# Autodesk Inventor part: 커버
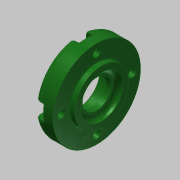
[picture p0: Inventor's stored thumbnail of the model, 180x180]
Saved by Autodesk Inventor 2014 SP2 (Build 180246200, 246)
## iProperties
Created: 2015-11
Part Number: 커버
Material: 알루미늄 6061
Document SubType Name: Modeling
Designer: mduedu
Density: 1 g/cm^3
Appearance: 매끄러움 - 짙은 산림 녹색
Author: mduedu
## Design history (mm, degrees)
sketch "스케치1"
  geometry: L1 (-7, 0)-(7, 0); L2 (-7, 0)-(-7, 26); L3 (-7, 26)-(4, 26); L4 (4, 26)-(4, 16); L5 (4, 16)-(7, 16); L6 (7, 16)-(7, 0); 2 further points
  constraints: 12 end point, 3 perpendicular, 2 parallel, 1 coincident, 1 horizontal, 1 midpoint
  dimensions: "d0" = 14 distance of L1.start L1.end; "d1" = 52 diameter of L3 L1; "d2" = 3 distance of L4.end L5.end; "d3" = 32 diameter of L5 L1
revolve "회전1" sketch "스케치1" stored, may be unused: angle "d4" = 90 deg
hole "구멍1" diameter "d7" = 25; stored, may be unused: countersink angle "d11" = 90 deg, drill point angle "d13" = 0 deg; dims "d5" = 10, "d6" = 10, "d8" = 6, "d9" = 4, "d10" = 2, "d12" = 3
hole "구멍2" diameter "d16" = 25; stored, may be unused: countersink angle "d20" = 90 deg, drill point angle "d22" = 0 deg; dims "d17" = 6, "d18" = 4, "d19" = 2, "d21" = 7.7, "d58" = 10, "d59" = 10
hole "구멍3" diameter "d25" = 17; stored, may be unused: countersink angle "d29" = 90 deg, drill point angle "d31" = 0 deg; dims "d23" = 10, "d24" = 10, "d26" = 6, "d27" = 4, "d28" = 2, "d30" = 4.2
chamfer "모따기1" distance "d32" = 0.6; stored, may be unused: second distance "d33" = 2, angle "d34" = 30 deg
fillet "모깎기1" dims "d35" = 0.3
fillet "모깎기2" dims "d36" = 3
fillet "모깎기3" dims "d37" = 3
fillet "모깎기4" dims "d38" = 0.3
sketch "스케치3" dims "d61" = 42
  geometry: C1 r 26 at (0, 0) reference; 2 further points
  constraints: 2 vertical alignment, 1 coincident, 2 other
hole "구멍4" sketch "스케치3" at (0, -21) diameter "d44" = 4.5; stored, may be unused: countersink angle "d48" = 90 deg, drill point angle "d50" = 0 deg; dims "d45" = 6, "d46" = 8, "d47" = 4.6, "d49" = 8
sketch "스케치4"
  geometry: L1 (-4, 0)-(-4, -4.69); L2 (4, 0)-(4, -4.69); A1 r 4 centre (0, 0) between (3.614, -1.714) and (-3.614, -1.714) reference; A2 r 26 centre (0, 21) between (-4, -4.69) and (4, -4.69) reference; 1 further point
  constraints: 4 end point, 4 point on circle, 2 tangent, 1 parallel, 1 vertical
extrude "돌출1" cut sketch "스케치4" stored distance "d51" = 0; taper "d52" = 0 deg
fillet "모깎기5" dims "d56" = 0.3
fillet "모깎기6" dims "d57" = 1
node "솔리드1"
pattern_circular "원형 패턴1" dims angle "d54" = 360 deg
